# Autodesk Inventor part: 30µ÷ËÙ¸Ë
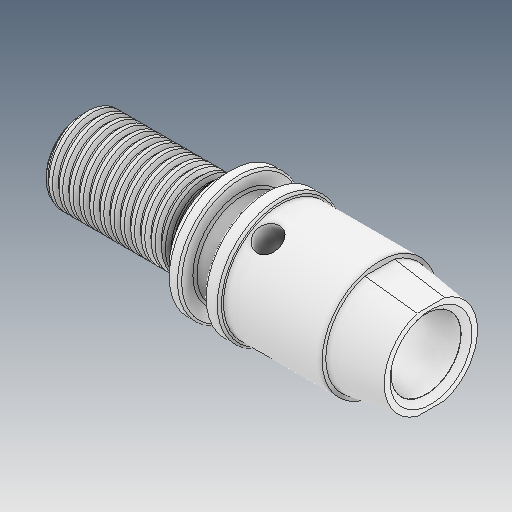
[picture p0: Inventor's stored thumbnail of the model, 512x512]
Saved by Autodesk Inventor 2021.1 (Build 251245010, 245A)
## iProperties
Created: 2021-05
Part Number: 30µ÷ËÙ¸Ë
Material: Ogólny
Document SubType Name: Modeling
Designer: user
Density: 1 g/cm^3
Appearance: Domyślna
Author: user
Revision Number: ÈÎºÎ
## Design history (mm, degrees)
feature "ÊäÈë1"
node "Bryła1"
